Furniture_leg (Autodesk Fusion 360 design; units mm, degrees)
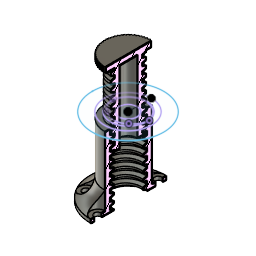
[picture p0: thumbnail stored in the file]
sketch "Sketch1" plane through (0, 0, 0) normal (0, 0, 1) x axis (1, 0, 0)
  line L1 (25, -25) -> (-10, -25)
  line L2 (25, 25) -> (25, -25)
  line L3 (-25, 25) -> (25, 25)
  line L4 (-25, -10) -> (-25, 25)
  line L5 (25, 25) -> (-25, -25)
  line L6 (-25, 25) -> (25, -25)
  circle C1 centre (0, 0) radius 10
  circle C2 centre (0, 0) radius 21
  circle C3 centre (0, 0) radius 17
  circle C4 centre (-0.2537, 16.9981) radius 2
  circle C5 centre (-14.8476, 8.2794) radius 2
  circle C6 centre (-14.594, -8.7187) radius 2
  circle C7 centre (0.2537, -16.9981) radius 2
  circle C8 centre (14.8476, -8.2794) radius 2
  circle C9 centre (14.594, 8.7187) radius 2
  arc A1 centre (-10, -10) radius 15 clockwise from (-10, -25) to (-25, -10)
  circle C10 centre (0, 0) radius 13
  circle C11 centre (-0.2537, 16.9981) radius 4
  circle C12 centre (-14.8476, 8.2794) radius 4
  circle C13 centre (-14.594, -8.7187) radius 4
  circle C14 centre (0.2537, -16.9981) radius 4
  circle C15 centre (14.8476, -8.2794) radius 4
  circle C16 centre (14.594, 8.7187) radius 4
  circle C17 centre (0, 0) radius 5
  point P1 (0, 0)
  point P2 (0, 0)
  point P5 (-0.2537, 16.9981)
  point P15 (0, 0)
  point P11 (-25, -25)
  point P13 (25, 25)
  point P14 (-25, 25)
  point P12 (25, -25)
  coincident P1 P2
  coincident C3 P5
  horizontal L1
  perpendicular L1 L2
  parallel L1 L3
  parallel L2 L4
  coincident L5 P15
  coincident L6 P15
  coincident P2 P15
  coincident P11 L1
  coincident P11 L4
  tangent L1 A1
  tangent L4 A1
  dimension "d1" diameter C1 = 20
  dimension "d2" = 11
  dimension "d3" = 7 (= "4 mm + 3 mm")
  dimension "d4" diameter C4 = 4
  dimension "d21" distance P13 P14 = 50
  dimension "d22" distance P12 P13 = 50
  dimension "d23" radius A1 = 15
  dimension "d24" = 3
  dimension "d29" distance C4 = 2
  dimension "d30" distance C5 = 2
  dimension "d31" distance C6 = 2
  dimension "d32" distance C7 = 2
  dimension "d33" distance C8 = 2
  dimension "d34" distance C9 = 2
  dimension "d69" = -5
  dimension "d6" C-Pattern1-Angle = 360
extrude "Extrude1" new body sketch "Sketch1" profile of C1 C2 C4 C5 C6 C7 C8 C9 C10 along normal blind 2
extrude "Extrude3" add sketch "Sketch1" profile of C1 C10 along normal blind 40 and against normal blind 0
fillet "Fillet1" radius 10
extrude "Extrude4" cut sketch "Sketch1" profile of C4 C5 C6 C7 C8 C9 along normal blind 13
extrude "Extrude5" cut sketch "Sketch1" profile of C4 C5 C6 C7 C8 C9 C11 C12 C13 C14 C15 C16 along normal blind 2 and along normal blind 14
thread "Thread3" ThreadOffset 2 ThreadLength 37
extrude "Extrude6" new body sketch "Sketch1" profile of C1 C17 along normal blind 43
thread "Thread4" ThreadOffset 3 ThreadLength 40
offset_faces "OffsetFaces3" distance -0.15
offset_faces "OffsetFaces4" distance -0.2
sketch "Sketch2" plane through (0, 0, 43) normal (0, 0, 1) x axis (-1, 0, 0)
  curve K1 (10.1142, -1.6627) -> (5.9498, 5.4872)
  curve K2 (-5.9498, 5.4872) -> (-10.1142, -1.6627)
  line L1 (0, -0.6201) -> (0, 0)
  line L2 (0, -13) -> (0, -0.6201)
  line L3 (0.3834, -12.9943) -> (0, -12.603)
  line L4 (-0.3991, -12.9939) -> (0, -12.603)
  circle C1 centre (0, 0) radius 9.775
  circle C2 centre (0, 0) radius 19.725
  circle C3 centre (0, 0) radius 13
  arc A1 centre (0, 0) radius 10.25 clockwise from (10.1142, -1.6627) to (-10.1142, -1.6627)
  arc A2 centre (0, 0) radius 8.0937 clockwise from (-5.9498, 5.4872) to (5.9498, 5.4872)
  circle C4 centre (0, 0) radius 5
  point P2 (0, 0)
  point P9 (0, 0)
  point P11 (0, -13)
  point P12 (0, -12.603)
  point P13 (0.3834, -12.9943)
  point P14 (-0.3991, -12.9939)
  coincident P2 P9
  vertical L1
  coincident C3 P11
  parallel L1 L2
  coincident L2 P12
  coincident C3 P13
  coincident C3 P14
  perpendicular L3 L4
extrude "Extrude7" add sketch "Sketch2" profile of C1 C3 K1 A1 K2 A2 L3 L4 against normal blind 3
extrude "Extrude11" cut sketch "Sketch2" profile of C3 L3 L4 against normal blind 3
circular_pattern "C-Pattern1" countU 60 TotalAngle 360
move "Move1"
